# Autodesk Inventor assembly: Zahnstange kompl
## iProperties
Created: 2006-11
Part Number: Zahnstange kompl
Cost Center: 0 kg
Document SubType Name: Assembly
Designer: Schmidt
Authority: 0 mm^3
Mass: 1720.28 g
Surface Area: 452.717 cm^2
Volume: 209.787 cm^3
Density: 8.20014 g/cm^3
SaveDate: 2004-08-02
SaveTime: 16:43
TotalMass: 0 kg
TotalVolume: 0 mm^3
Author: Schmidt
